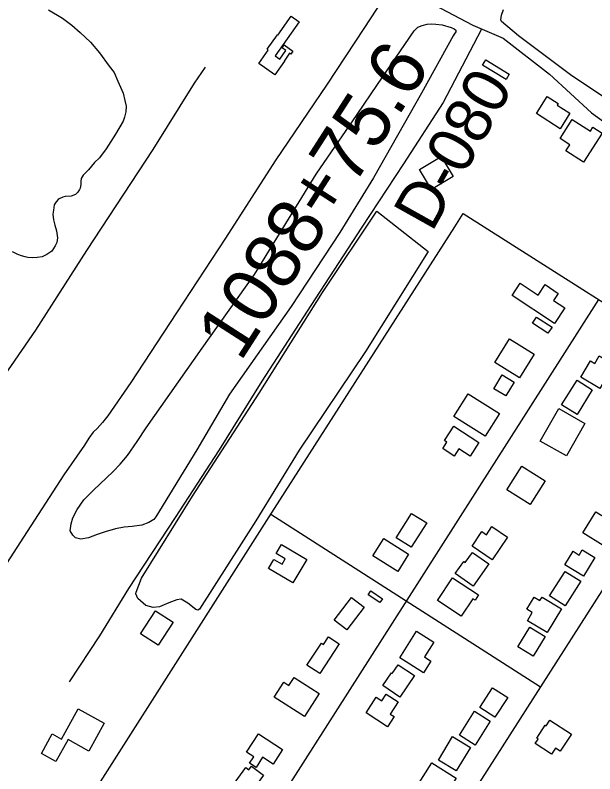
# Model space of a CAD drawing. Extents: x 3855477 to 3893699, y 299188 to 325115.
# Drawn here: x 3861465 to 3862509, y 311441 to 312808 of the extents above; entities that cross this region are included whole.
import ezdxf

# ---------------------------------------------------------------- set-up
doc = ezdxf.new("R2010")
doc.units = 0
for name, color, linetype in [('V-BLDG-OTLN', 7, 'Continuous'), ('V-RIVR-RANG-IDEN', 7, 'Continuous'), ('V-ROAD-CNTR', 7, 'Continuous'), ('V-SITE-VEGE', 7, 'Continuous'), ('V-SURV-IDEN', 7, 'Continuous'), ('V-TOPO-SHOR', 7, 'Continuous')]:
    doc.layers.add(name, color=color, linetype=linetype)

msp = doc.modelspace()

# ---------------------------------------------------------------- linework, layer by layer
at = {"layer": 'V-BLDG-OTLN'}
for points in [[(3861932.7, 312700.9), (3861903.9, 312721.3), (3861921, 312745.6), (3861919, 312746.9), (3861937.5, 312773.1), (3861938.4, 312772.5), (3861962.3, 312806.3), (3861976.8, 312796.1), (3861933.6, 312735), (3861941.6, 312729.3), (3861952.8, 312745), (3861946, 312749.8), (3861949.6, 312754.8), (3861965.3, 312743.7), (3861961.5, 312738.1), (3861959.4, 312739.6), (3861949.4, 312725.5), (3861949.9, 312725.2)], [(3862313.1, 312727.7), (3862355.2, 312702), (3862349.4, 312692.4), (3862307.2, 312718.1)], [(3862447, 312603.8), (3862404, 312631.1), (3862423.7, 312662), (3862443.4, 312649.5), (3862441.3, 312646.2), (3862464.5, 312631.5)], [(3862446.8, 312586.1), (3862468.8, 312620.5), (3862501.3, 312599.6), (3862505.6, 312606.4), (3862522.4, 312595.6), (3862488.8, 312543.3), (3862456.9, 312563.7), (3862464.1, 312575)], [(3862254, 312517.9), (3862214.8, 312494.3), (3862193.3, 312530.2), (3862232.5, 312553.7)], [(3862407.3, 312304.1), (3862419.8, 312322.9), (3862443.6, 312307.1), (3862435.1, 312294.3), (3862455.3, 312280.9), (3862436.7, 312252.7), (3862360.2, 312303.4), (3862374.9, 312325.6)], [(3862404.5, 312264.4), (3862432.3, 312246.4), (3862425, 312235.2), (3862397.3, 312253.2)], [(3862355.7, 312225.2), (3862400.3, 312197.8), (3862373.9, 312154.8), (3862329.2, 312182.3)], [(3862517.4, 312194.3), (3862546.7, 312176.7), (3862537.4, 312161.2), (3862544.4, 312157), (3862532.2, 312136.8), (3862522.4, 312142.7), (3862518.2, 312135.7), (3862484.2, 312156.2), (3862501.8, 312185.4), (3862509.3, 312180.8)], [(3862364.3, 312147.3), (3862349, 312122.3), (3862327.4, 312135.4), (3862342.6, 312160.5)], [(3862504.9, 312133.5), (3862477.3, 312088.9), (3862449.5, 312106.2), (3862477.3, 312150.6)], [(3862281.4, 312126.2), (3862337.6, 312090.9), (3862311.8, 312049.7), (3862255.6, 312085)], [(3862444.4, 312099.5), (3862491.6, 312072.6), (3862458.4, 312014.2), (3862411.1, 312041.1)], [(3862255.2, 312067.9), (3862300.5, 312038.2), (3862284.5, 312013.8), (3862264.4, 312026.9), (3862256, 312014), (3862235.3, 312027.6), (3862243, 312039.3), (3862238.4, 312042.3)], [(3862419.7, 311969.2), (3862392.8, 311926.7), (3862350.9, 311953.1), (3862377.7, 311995.7)], [(3862206.4, 311893.4), (3862178.7, 311849.6), (3862151.6, 311866.8), (3862179.2, 311910.5)], [(3862511.5, 311913.5), (3862548.2, 311890.7), (3862524.5, 311852.7), (3862487.8, 311875.5)], [(3862352, 311867.7), (3862324.4, 311827.1), (3862288.1, 311851.8), (3862305.8, 311877.9), (3862314.1, 311872.2), (3862324, 311886.8)], [(3861944.9, 311854.9), (3861990.3, 311827.9), (3861965, 311785.6), (3861921.5, 311811.6), (3861931.1, 311827.8), (3861945.8, 311819), (3861951.5, 311828.6), (3861935.1, 311838.4)], [(3862129, 311865.5), (3862173.9, 311837.5), (3862154.3, 311806.1), (3862109.4, 311834.2)], [(3862318.4, 311819.7), (3862290.4, 311779.5), (3862257.9, 311802.2), (3862273.1, 311824), (3862276, 311822), (3862288.8, 311840.4)], [(3862486.7, 311844.9), (3862509.3, 311831.3), (3862489.1, 311797.6), (3862455.4, 311817.9), (3862470.1, 311842.4), (3862481.1, 311835.7)], [(3862427.9, 311762.2), (3862456, 311806.3), (3862483.9, 311788.6), (3862455.9, 311744.4)], [(3862252.8, 311794.5), (3862299.7, 311763.7), (3862293.5, 311754.3), (3862289.4, 311757), (3862268.8, 311725.6), (3862226, 311753.7)], [(3862105.5, 311771), (3862126.5, 311757), (3862121.9, 311750), (3862100.8, 311764)], [(3862093.7, 311742), (3862062.6, 311701.1), (3862039.8, 311718.4), (3862071, 311759.3)], [(3862386.7, 311737.9), (3862400, 311759.8), (3862410.4, 311753.5), (3862414.4, 311760), (3862449.3, 311738.8), (3862423.4, 311696), (3862388, 311717.4), (3862396.7, 311731.9)], [(3861749.6, 311714.5), (3861722.8, 311673.1), (3861690.5, 311694), (3861717.4, 311735.4)], [(3862370.6, 311670.4), (3862392.3, 311705.6), (3862419.8, 311688.6), (3862398.2, 311653.5)], [(3862158, 311650.3), (3862188.3, 311698.3), (3862219.1, 311678.8), (3862202.3, 311652.2), (3862214.1, 311644.7), (3862200.7, 311623.4)], [(3862048.5, 311675.7), (3862013.7, 311622.2), (3861990.7, 311637.1), (3862016.6, 311676.9), (3862020.6, 311674.2), (3862029.6, 311688)], [(3862158.3, 311579.8), (3862127.6, 311600.6), (3862143, 311623.2), (3862144.2, 311622.3), (3862154.8, 311638), (3862184.2, 311618.4)], [(3862012.5, 311586.4), (3861986, 311545), (3861931.7, 311579.7), (3861948.7, 311606.5), (3861958.2, 311600.4), (3861967.5, 311615.1)], [(3862302.1, 311560.7), (3862324.9, 311596.6), (3862352.6, 311579), (3862329.4, 311543.3)], [(3862135.9, 311526.4), (3862097.5, 311551.3), (3862115.6, 311579.4), (3862125.4, 311573.1), (3862133.2, 311585.1), (3862154.9, 311571.1), (3862140.6, 311549.1), (3862147.6, 311544.6)], [(3861625.2, 311532.6), (3861597.5, 311482.6), (3861560.2, 311503.2), (3861538.3, 311463.7), (3861512, 311478.2), (3861531.5, 311513.4), (3861548.4, 311504), (3861578.6, 311558.4)], [(3862265.3, 311511.1), (3862292.6, 311554.5), (3862321, 311536.6), (3862293.8, 311493.3)], [(3862428.1, 311538.4), (3862467.2, 311513.2), (3862447.2, 311482.2), (3862438.4, 311487.9), (3862431.4, 311477.1), (3862402.1, 311496), (3862407.4, 311504.2), (3862404.6, 311506), (3862419.7, 311529.3), (3862421.5, 311528.1)], [(3861903.1, 311513.7), (3861946.8, 311485.3), (3861929.8, 311459), (3861910.8, 311471.3), (3861898.9, 311453.1), (3861887.2, 311460.7), (3861894.7, 311472.3), (3861881.7, 311480.8)], [(3862227.5, 311466.3), (3862253.1, 311508.5), (3862285.2, 311489), (3862259.5, 311446.8)], [(3862215.6, 311461.3), (3862259.3, 311433.7), (3862249, 311417.4), (3862238.3, 311424.2), (3862221.8, 311397.9), (3862188.7, 311418.8)], [(3861912.5, 311439.2), (3861884.1, 311399.8), (3861856.3, 311419.8), (3861880.2, 311453), (3861886, 311448.8), (3861890.5, 311455)]]:
    msp.add_lwpolyline(points, close=True, dxfattribs=at)
at = {"layer": 'V-ROAD-CNTR'}
for points in [[(3862208.5, 312832.9), (3862289.4, 312790.1), (3862344.1, 312767), (3862427.9, 312701.8), (3862503.3, 312632.2), (3862604.8, 312559), (3862731.9, 312500.5), (3862961.5, 312402.9), (3863055.6, 312366.2), (3863201.4, 312292.2), (3863304.3, 312229.8), (3863438.2, 312163), (3863561.4, 312083.6)], [(3861471.7, 311196), (3861922.4, 311904.6), (3862257.2, 312427.1), (3862272.2, 312451), (3862728.2, 312161.4), (3862759.8, 312143.1)], [(3862931.8, 312412.4), (3862591.1, 311879.2), (3862236.3, 311324), (3862081.5, 311086.2)], [(3862516.2, 312296), (3862166.6, 311747.8), (3861723.8, 311053.9)], [(3861925.3, 311909.2), (3862411.6, 311598.3)]]:
    msp.add_lwpolyline(points, dxfattribs=at)
at = {"layer": 'V-SITE-VEGE'}
msp.add_lwpolyline([(3862588.1, 312619.1), (3862467.7, 312699.3), (3862371.8, 312770.9), (3862341.1, 312796.9), (3862339.9, 312799.9), (3862341.2, 312808.3), (3862344.9, 312818.4)], dxfattribs=at)
for points in [[(3862254.2, 312771.1), (3862196.8, 312667.8), (3862110.3, 312515.3), (3862050.1, 312416.8), (3861961.9, 312283.5), (3861850.8, 312125.3), (3861792.4, 312025), (3861718.1, 311904.6), (3861714.5, 311899.9), (3861705.5, 311894), (3861692.9, 311889.4), (3861675.5, 311887.2), (3861661.2, 311885.6), (3861645.6, 311882.8), (3861627.1, 311877.6), (3861612.7, 311872.4), (3861597.1, 311866.6), (3861583.3, 311864.4), (3861573.8, 311866.9), (3861568.5, 311871.7), (3861563.8, 311879.5), (3861565.7, 311892), (3861568.8, 311902.8), (3861576.7, 311917.6), (3861588.3, 311935.4), (3861605.8, 311952.5), (3861629.4, 311974.9), (3861641.4, 311986.1), (3861654.1, 311999.1), (3861667.4, 312015.1), (3861684.4, 312040), (3861700.9, 312064.9), (3861801.6, 312208.3), (3861896.3, 312341), (3862007.1, 312521.9), (3862081.1, 312629.1), (3862117.6, 312683.6), (3862183.8, 312780.2), (3862190.4, 312786.7), (3862198.2, 312789.6), (3862207.2, 312791.9), (3862215, 312793), (3862222.7, 312792.3), (3862234.1, 312791), (3862250.7, 312786), (3862256.1, 312783.6), (3862259.1, 312781.2), (3862259, 312778.2), (3862256, 312774)], [(3862209.1, 312382.8), (3862096, 312202.5), (3861976.3, 312024.7), (3861898.4, 311897.2), (3861796.9, 311738.3), (3861793.9, 311736.6), (3861790.3, 311737.8), (3861776.1, 311748.7), (3861764.2, 311756), (3861756.4, 311754.9), (3861742, 311749.7), (3861725.2, 311742.1), (3861713.3, 311741.1), (3861700.2, 311744.8), (3861686, 311757.5), (3861682.5, 311765.9), (3861683.1, 311768.9), (3861692.4, 311793.9), (3861784.2, 311941.5), (3861904.6, 312127.1), (3862018.4, 312308.5), (3862116.8, 312455.5)]]:
    msp.add_lwpolyline(points, close=True, dxfattribs=at)
at = {"layer": 'V-TOPO-SHOR'}
for points in [[(3862149, 312870.5), (3862093.3, 312784.2), (3862027.1, 312684.1), (3861933.1, 312545.9), (3861844, 312406.5), (3861755.6, 312272), (3861673.3, 312146.5), (3861631.9, 312086.2), (3861622, 312074.7), (3861612.8, 312063.9), (3861605.4, 312057.3), (3861597.4, 312046.5), (3861589.9, 312033.8), (3861552.8, 311980.1), (3861479.8, 311867.9), (3861424.8, 311783.4), (3861377.7, 311706.7), (3861288.1, 311575.8), (3861216.2, 311458.1), (3861133.4, 311334.5), (3861029.4, 311176.4), (3860957.6, 311063.5), (3860942.8, 311040.6)], [(3861524.9, 312818), (3861549.9, 312802.8), (3861567, 312790.1), (3861581.8, 312777.4), (3861600.7, 312759.8), (3861616.6, 312740.5), (3861634.3, 312716.4), (3861643.1, 312705), (3861650.1, 312689.4), (3861654.7, 312678.6), (3861659.4, 312667.8), (3861662.2, 312654.6), (3861665.1, 312644.4), (3861664.4, 312634.3), (3861661.9, 312624.7), (3861659.4, 312617.6), (3861645.4, 312593.9), (3861629, 312567.8), (3861616.9, 312551.2), (3861607.8, 312542.9), (3861596.9, 312529.9), (3861587.2, 312519.9), (3861583.6, 312514), (3861582.9, 312508.6), (3861582.9, 312503.2), (3861582.2, 312496.7), (3861581, 312494.3), (3861577.9, 312489.5), (3861573.7, 312485.4), (3861565.9, 312482.5), (3861555.1, 312481.4), (3861551, 312480.3), (3861544.4, 312477.4), (3861542, 312476.2), (3861538.9, 312472.1), (3861535.3, 312466.7), (3861534, 312457.2), (3861532.7, 312450), (3861533.8, 312439.9), (3861536.1, 312430.3), (3861539.5, 312419.5), (3861541.2, 312406.9), (3861539.9, 312398.6), (3861536.8, 312392.7), (3861530.7, 312383.2), (3861521.7, 312377.3), (3861513.3, 312373.2), (3861504.3, 312371.5), (3861496, 312371), (3861487.6, 312371.7), (3861482.8, 312373), (3861476.3, 312374.8)], [(3862304.8, 312782.2), (3862236.2, 312651.3), (3862164.4, 312540.6), (3862089.5, 312426.4), (3861997.7, 312285), (3861909.6, 312149), (3861832.2, 312025.3), (3861753.1, 311903.4), (3861669.2, 311775.1), (3861616.7, 311690.3), (3861562.3, 311607.2)], [(3860514.3, 311585.1), (3860639.4, 311516.6), (3860766.8, 311433.3), (3860795.8, 311414.2), (3860860.2, 311371.6), (3860912.8, 311338.7), (3860915.8, 311338.6), (3860918.1, 311339.2), (3860926.5, 311349.7), (3861011, 311479.4), (3861099.1, 311623.2), (3861200.4, 311783.8), (3861289.6, 311919.4), (3861388.5, 312077.1), (3861502.2, 312240.6), (3861593.9, 312384.4), (3861713.7, 312566.6), (3861788, 312685.8), (3861807.8, 312714.5)], [(3861476.3, 312374.8), (3861469.8, 312377.3), (3861460.3, 312382.2)]]:
    msp.add_lwpolyline(points, dxfattribs=at)

# ---------------------------------------------------------------- texts
at = {"layer": 'V-RIVR-RANG-IDEN'}
msp.add_text('D-080', height=83, rotation=60.7713, dxfattribs=at).set_placement((3862215.7, 312415.7))
at = {"layer": 'V-SURV-IDEN'}
msp.add_text('1088+75.6', height=100, rotation=57.2625, dxfattribs=at).set_placement((3861870.7, 312182.1))

doc.saveas('drawing.dxf')
